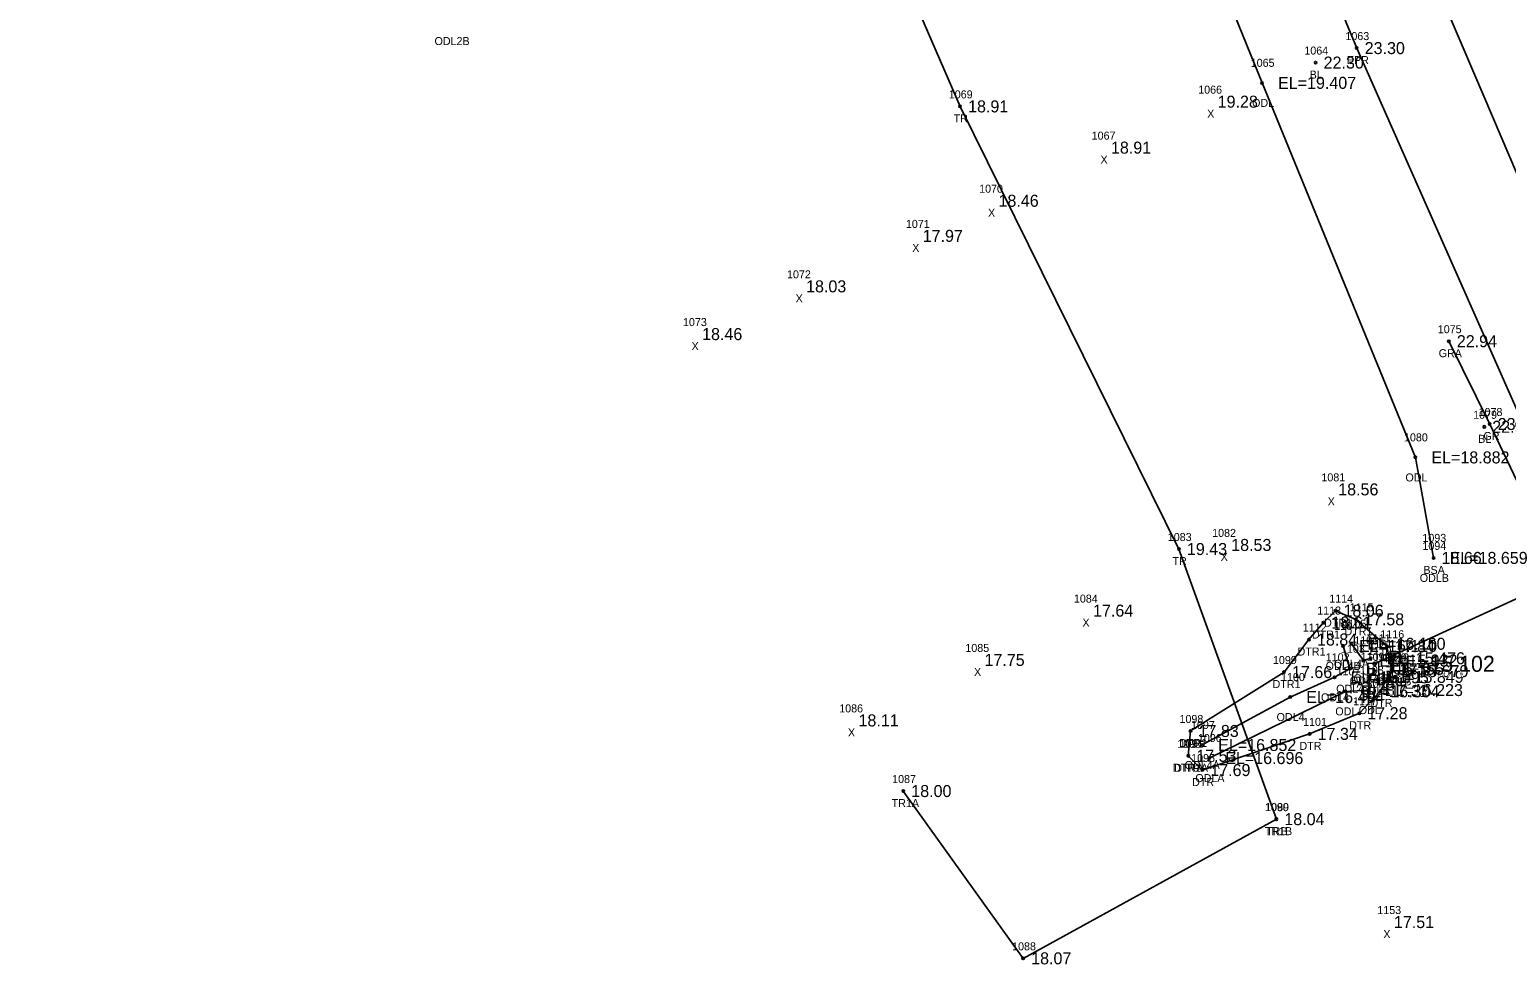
# Model space of a CAD drawing. Extents: x 2042117 to 2045853, y 303080 to 309569.
# Drawn here: x 2042812.2 to 2042996.7, y 306487.7 to 306604.6 of the extents above; entities that cross this region are included whole.
import ezdxf

# ---------------------------------------------------------------- set-up
doc = ezdxf.new("R2010")
doc.units = 0
for name, color, linetype in [('RD_DTM_BkLn_txCode', 7, 'Continuous'), ('RD_EX_DR_Pipe', 7, 'Continuous'), ('RD_EX_DR_Pipe_txCode', 7, 'Continuous'), ('RD_EX_GuardRail', 7, 'Continuous'), ('RD_EX_GuardRail_txCode', 7, 'Continuous'), ('RD_EX_H2O', 7, 'Continuous'), ('RD_EX_H2O_txCode', 7, 'Continuous'), ('RD_EX_Misc_txCode', 7, 'Continuous'), ('RD_EX_Road', 7, 'Continuous'), ('RD_EX_Road_txCode', 7, 'Continuous'), ('RD_EX_TX_GuardRail_ELEV', 7, 'Continuous'), ('RD_EX_TX_H2O_ELEV', 7, 'Continuous'), ('RD_EX_TX_Misc_ELEV', 7, 'Continuous'), ('RD_EX_TX_Road_ELEV', 7, 'Continuous'), ('RD_EX_TX_VEG_ELEV', 7, 'Continuous'), ('RD_EX_VEG', 7, 'Continuous'), ('RD_EX_VEG_txCode', 7, 'Continuous'), ('RD_HC_Cl', 7, 'Continuous'), ('RD_SMD_Locator', 7, 'Continuous'), ('RD_TX_Pipe_ElevEX', 7, 'Continuous')]:
    doc.layers.add(name, color=color, linetype=linetype)

msp = doc.modelspace()

# ---------------------------------------------------------------- linework, layer by layer
at = {"layer": 'RD_EX_DR_Pipe'}
msp.add_line((2042980.25, 306525.37), (2043055.2, 306559.76), dxfattribs=at)
at = {"layer": 'RD_EX_GuardRail'}
msp.add_lwpolyline([(2042989.52, 306565.65), (2042994.63, 306555.31), (2043016.03, 306510.44), (2043038.99, 306465.35), (2043062.42, 306421.45), (2043086.95, 306378), (2043112.8, 306335.35), (2043139.38, 306293.6), (2043167.12, 306252.13), (2043196.01, 306211.01), (2043226.01, 306171.01), (2043257.1, 306132.34), (2043288.76, 306093.67), (2043353.25, 306016.86), (2043419.08, 305941.69), (2043443.37, 305914.98)], dxfattribs=at)
at = {"layer": 'RD_EX_H2O'}
for points in [[(2042812.2, 307117.75), (2042817.66, 307076.99), (2042828.97, 307027.39), (2042840.42, 306978.95), (2042848.44, 306929.66), (2042859.84, 306880.36), (2042873.68, 306831.67), (2042888.54, 306783.43), (2042900.59, 306749.27), (2042902.9, 306733.67), (2042926.04, 306688.21), (2042936.45, 306668.37), (2042947.44, 306643.99), (2042966.18, 306597.91), (2042985.34, 306551.14), (2042987.61, 306538.59)], [(2042956.97, 306513.88), (2042957.25, 306516.98), (2042968.93, 306524.34), (2042972.05, 306528.4), (2042973.86, 306530.52), (2042975.36, 306532), (2042977.92, 306530.92), (2042981.78, 306527.56), (2042982.37, 306524.67)], [(2042958.7, 306515.23), (2042969.7, 306521.22), (2042975.25, 306523.68), (2042977.15, 306524.75), (2042976.3, 306527.61)], [(2042977.35, 306527.87), (2042978.84, 306525.78), (2042979.77, 306526.06)], [(2042956.97, 306513.88), (2042958.72, 306512.1), (2042972.13, 306516.62), (2042978.34, 306519.2), (2042981, 306521.98), (2042982.37, 306524.67)], [(2042959.58, 306513.6), (2042976.59, 306521.93), (2042979.52, 306522.09), (2042979.61, 306523.74), (2042980.2, 306524.46)]]:
    msp.add_lwpolyline(points, dxfattribs=at)
at = {"layer": 'RD_EX_Road'}
msp.add_lwpolyline([(2042895.94, 306837.56), (2042909.76, 306789.89), (2042925.08, 306742.02), (2042941.49, 306695.02), (2042958.75, 306648.66), (2042978.01, 306602.25), (2042998.08, 306556.93), (2043019.38, 306511.63), (2043041.84, 306466.86), (2043065.03, 306422.83), (2043089.72, 306379.65), (2043115.12, 306336.87), (2043141.61, 306295.02)], dxfattribs=at)
at = {"layer": 'RD_EX_VEG'}
for points in [[(2042864.25, 306612.56), (2042883.28, 306667.35), (2042906.08, 306641.46), (2042916.37, 306622.92), (2042928.46, 306594.97), (2042955.8, 306539.7), (2042967.97, 306505.97)], [(2042921.36, 306509.48), (2042936.34, 306488.59), (2042967.97, 306505.97)]]:
    msp.add_lwpolyline(points, dxfattribs=at)
at = {"layer": 'RD_HC_Cl'}
msp.add_arc((2044751.25, 307348.43), 1911.29, 137.68184, 219.86836, dxfattribs=at)
at = {"layer": 'RD_SMD_Locator'}
for centre, radius in [((2042978.01, 306602.25), 0.15), ((2042972.88, 306600.44), 0.15), ((2042966.18, 306597.91), 0.15), ((2042928.46, 306594.97), 0.15), ((2042989.52, 306565.65), 0.15), ((2042993.94, 306554.96), 0.15), ((2042994.63, 306555.31), 0.15), ((2042985.34, 306551.14), 0.15), ((2042955.8, 306539.7), 0.15), ((2042987.61, 306538.59), 0.15), ((2042987.61, 306538.59), 0.15), ((2042975.36, 306532), 0.15), ((2042973.86, 306530.52), 0.15), ((2042977.92, 306530.92), 0.15), ((2042972.05, 306528.4), 0.15), ((2042976.3, 306527.61), 0.15), ((2042977.35, 306527.87), 0.15), ((2042979.77, 306526.06), 0.15), ((2042981.78, 306527.56), 0.15), ((2042968.93, 306524.34), 0.15), ((2042977.15, 306524.75), 0.15), ((2042978.84, 306525.78), 0.15), ((2042980.25, 306525.37), 0.2), ((2042980.2, 306524.46), 0.15), ((2042982.37, 306524.67), 0.15), ((2042982.37, 306524.67), 0.15), ((2042975.25, 306523.68), 0.15), ((2042979.61, 306523.74), 0.15), ((2042969.7, 306521.22), 0.15), ((2042976.59, 306521.93), 0.15), ((2042979.52, 306522.09), 0.15), ((2042981, 306521.98), 0.15), ((2042978.34, 306519.2), 0.15), ((2042957.25, 306516.98), 0.15), ((2042958.7, 306515.23), 0.15), ((2042972.13, 306516.62), 0.15), ((2042956.97, 306513.88), 0.15), ((2042956.97, 306513.88), 0.15), ((2042959.58, 306513.6), 0.15), ((2042958.72, 306512.1), 0.15), ((2042921.36, 306509.48), 0.15), ((2042967.97, 306505.97), 0.15), ((2042967.97, 306505.97), 0.15), ((2042936.34, 306488.59), 0.15)]:
    msp.add_circle(centre, radius, dxfattribs=at)

# ---------------------------------------------------------------- texts
at = {"layer": 'RD_DTM_BkLn_txCode'}
for s, p in [('1064', (2042971.47, 306601.44)), ('BL', (2042972.13, 306598.44)), ('1079', (2042992.56, 306555.96)), ('BL', (2042993.19, 306552.96)), ('1094', (2042986.22, 306539.59)), ('BSA', (2042986.34, 306536.59))]:
    msp.add_text(s, height=1, dxfattribs=at).set_placement(p)
at = {"layer": 'RD_EX_DR_Pipe_txCode'}
for s, p in [('1121', (2042979.47, 306527.37)), ('PA 30RC', (2042977.09, 306522.37))]:
    msp.add_text(s, height=1, dxfattribs=at).set_placement(p)
at = {"layer": 'RD_EX_GuardRail_txCode'}
for s, p in [('1075', (2042988.14, 306566.65)), ('GRA', (2042988.25, 306563.65)), ('1078', (2042993.24, 306556.31)), ('GR', (2042993.85, 306553.31))]:
    msp.add_text(s, height=1, dxfattribs=at).set_placement(p)
at = {"layer": 'RD_EX_H2O_txCode'}
for s, p in [('ODL2B', (2042862.8, 306602.63)), ('1065', (2042964.77, 306599.91)), ('ODL', (2042964.94, 306594.91)), ('1080', (2042983.92, 306553.14)), ('ODL', (2042984.1, 306548.14)), ('1093', (2042986.22, 306540.59)), ('ODLB', (2042985.89, 306535.59)), ('1114', (2042974.58, 306533)), ('1113', (2042973.08, 306531.52)), ('1115', (2042977.14, 306531.92)), ('1112', (2042971.27, 306529.4)), ('DTR1', (2042973.93, 306530)), ('1104', (2042975.19, 306529.61)), ('1105', (2042976.24, 306529.87)), ('DTR1', (2042976.48, 306528.92)), ('DTR1', (2042972.42, 306528.52)), ('1106', (2042977.71, 306527.78)), ('1111', (2042979.27, 306528.06)), ('1116', (2042980.97, 306528.56)), ('1099', (2042967.55, 306525.34)), ('DTR1', (2042970.62, 306526.4)), ('1102', (2042974.14, 306525.68)), ('1103', (2042976.04, 306526.75)), ('1109', (2042978.51, 306525.74)), ('1110', (2042979.38, 306526.46)), ('DTR1', (2042980.34, 306525.56)), ('1120', (2042981.26, 306525.67)), ('1119', (2042981.59, 306525.67)), ('ODL4B', (2042974.13, 306524.61)), ('ODL4A', (2042975.16, 306524.87)), ('1107', (2042975.49, 306523.93)), ('1108', (2042978.41, 306524.09)), ('DTR1', (2042967.5, 306522.34)), ('1100', (2042968.56, 306523.22)), ('ODL4', (2042975.45, 306521.75)), ('ODL4', (2042977.15, 306522.78)), ('ODL4B', (2042977.61, 306523.06)), ('1118', (2042980.22, 306522.98)), ('DTR1B', (2042980.46, 306522.67)), ('DTRB', (2042980.62, 306522.67)), ('ODL4', (2042973.55, 306520.68)), ('1117', (2042977.56, 306520.2)), ('ODL', (2042978.37, 306520.74)), ('ODLB', (2042978.48, 306521.46)), ('DTR', (2042979.74, 306519.98)), ('1098', (2042955.87, 306517.98)), ('ODL4', (2042968, 306518.22)), ('ODL', (2042975.34, 306518.93)), ('ODL', (2042978.27, 306519.09)), ('1097', (2042957.31, 306517.23)), ('1101', (2042971.31, 306517.62)), ('DTR', (2042977.07, 306517.2)), ('1092', (2042955.59, 306514.88)), ('DTR1', (2042955.82, 306514.98)), ('1091', (2042955.87, 306514.88)), ('1096', (2042958.17, 306515.6)), ('DTR', (2042970.86, 306514.62)), ('1095', (2042957.33, 306513.1)), ('DTR1A', (2042955.05, 306511.88)), ('DTRA', (2042955.22, 306511.88)), ('ODL4A', (2042956.52, 306512.23)), ('ODLA', (2042957.85, 306510.6)), ('DTR', (2042957.45, 306510.1))]:
    msp.add_text(s, height=1, dxfattribs=at).set_placement(p)
at = {"layer": 'RD_EX_Misc_txCode'}
for s, p in [('1066', (2042958.21, 306596.56)), ('X', (2042959.33, 306593.56)), ('1067', (2042944.9, 306590.82)), ('X', (2042946, 306587.82)), ('1070', (2042930.84, 306584.19)), ('X', (2042931.95, 306581.19)), ('1071', (2042921.69, 306579.8)), ('X', (2042922.48, 306576.8)), ('1072', (2042906.84, 306573.5)), ('X', (2042907.91, 306570.5)), ('1073', (2042893.84, 306567.54)), ('X', (2042894.91, 306564.54)), ('1081', (2042973.6, 306548.15)), ('X', (2042974.39, 306545.15)), ('1082', (2042959.95, 306541.21)), ('X', (2042961.02, 306538.21)), ('1084', (2042942.68, 306533.01)), ('X', (2042943.75, 306530.01)), ('1085', (2042929.12, 306526.85)), ('X', (2042930.2, 306523.85)), ('1086', (2042913.36, 306519.3)), ('X', (2042914.45, 306516.3)), ('1153', (2042980.59, 306494.12)), ('X', (2042981.34, 306491.12))]:
    msp.add_text(s, height=1, dxfattribs=at).set_placement(p)
at = {"layer": 'RD_EX_Road_txCode'}
for s, p in [('1063', (2042976.6, 306603.25)), ('EPR', (2042976.78, 306600.25))]:
    msp.add_text(s, height=1, dxfattribs=at).set_placement(p)
at = {"layer": 'RD_EX_TX_GuardRail_ELEV'}
for s, p in [('22.94', (2042990.52, 306564.9)), ('23.19', (2042995.63, 306554.56))]:
    msp.add_text(s, height=1.5, dxfattribs=at).set_placement(p)
at = {"layer": 'RD_EX_TX_H2O_ELEV'}
for s, p in [('EL=19.407', (2042968.18, 306597.16)), ('EL=18.882', (2042987.34, 306550.39)), ('EL=18.659', (2042989.61, 306537.84)), ('18.06', (2042976.36, 306531.25)), ('18.61', (2042974.86, 306529.77)), ('17.58', (2042978.92, 306530.17)), ('18.84', (2042973.05, 306527.65)), ('EL=16.110', (2042978.3, 306526.86)), ('EL=16.160', (2042979.35, 306527.12)), ('17.84', (2042982.78, 306526.81)), ('EL=15.932', (2042980.84, 306525.03)), ('EL=15.476', (2042981.77, 306525.31)), ('17.66', (2042969.93, 306523.59)), ('EL=16.095', (2042977.25, 306522.93)), ('EL=16.155', (2042979.15, 306524)), ('EL=15.849', (2042981.61, 306522.99)), ('EL=15.670', (2042982.2, 306523.71)), ('17.97', (2042983.37, 306523.92)), ('17.97', (2042983.37, 306523.92)), ('EL=16.304', (2042978.59, 306521.18)), ('EL=16.223', (2042981.52, 306521.34)), ('17.32', (2042982, 306521.23)), ('EL=16.494', (2042971.7, 306520.47)), ('17.28', (2042979.34, 306518.45)), ('17.83', (2042958.25, 306516.23)), ('17.34', (2042973.13, 306515.87)), ('EL=16.852', (2042960.7, 306514.48)), ('17.53', (2042957.97, 306513.13)), ('17.53', (2042957.97, 306513.13)), ('EL=16.696', (2042961.58, 306512.85)), ('17.69', (2042959.72, 306511.35))]:
    msp.add_text(s, height=1.5, dxfattribs=at).set_placement(p)
at = {"layer": 'RD_EX_TX_Misc_ELEV'}
for s, p in [('22.30', (2042973.88, 306599.69)), ('19.28', (2042960.64, 306594.81)), ('18.91', (2042947.31, 306589.07)), ('18.46', (2042933.26, 306582.44)), ('17.97', (2042923.79, 306578.05)), ('18.03', (2042909.22, 306571.75)), ('18.46', (2042896.23, 306565.79)), ('22.93', (2042994.94, 306554.21)), ('18.56', (2042975.7, 306546.4)), ('18.53', (2042962.33, 306539.46)), ('18.66', (2042988.61, 306537.84)), ('17.64', (2042945.07, 306531.26)), ('17.75', (2042931.51, 306525.1)), ('18.11', (2042915.77, 306517.55)), ('17.51', (2042982.66, 306492.37))]:
    msp.add_text(s, height=1.5, dxfattribs=at).set_placement(p)
at = {"layer": 'RD_EX_TX_Road_ELEV'}
msp.add_text('23.30', height=1.5, dxfattribs=at).set_placement((2042979.01, 306601.5))
at = {"layer": 'RD_EX_TX_VEG_ELEV'}
for s, p in [('18.91', (2042929.46, 306594.22)), ('19.43', (2042956.8, 306538.95)), ('18.00', (2042922.36, 306508.73)), ('18.04', (2042968.97, 306505.22)), ('18.04', (2042968.97, 306505.22)), ('18.07', (2042937.34, 306487.84))]:
    msp.add_text(s, height=1.5, dxfattribs=at).set_placement(p)
at = {"layer": 'RD_EX_VEG_txCode'}
for s, p in [('1069', (2042927.05, 306595.97)), ('TR', (2042927.66, 306592.97)), ('1083', (2042954.41, 306540.7)), ('TR', (2042955, 306537.7)), ('1087', (2042919.97, 306510.48)), ('TR1A', (2042919.91, 306507.48)), ('1090', (2042966.54, 306506.97)), ('1089', (2042966.58, 306506.97)), ('TR1B', (2042966.53, 306503.97)), ('TRB', (2042966.7, 306503.97)), ('1088', (2042934.96, 306489.59))]:
    msp.add_text(s, height=1, dxfattribs=at).set_placement(p)
at = {"layer": 'RD_TX_Pipe_ElevEX'}
msp.add_text('EL=15.102', height=2, dxfattribs=at).set_placement((2042982.25, 306524.37))

doc.saveas('drawing.dxf')
